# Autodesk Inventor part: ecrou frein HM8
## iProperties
Shininess: 20.0
Angle Display Precision: 2
Document Length Units: 11269
Document Angle Units: 11279
Document Time Units: 11290
Document Mass Units: 11283
Document Length Units Precision: 3
Document Angle Units Precision: 2
Compacted: True
Created: 2002-04
Part Number: ecrou frein HM8
Material: Par défaut
Document SubType Name: Modélisation
Designer: thchene
Density: 0.0
Volumn: 0.0
Area: 0.0
PropertySet Name: Model Information
Control State: 0
Master: False
Checked Out: False
Author: thchene
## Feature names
1. Base1
